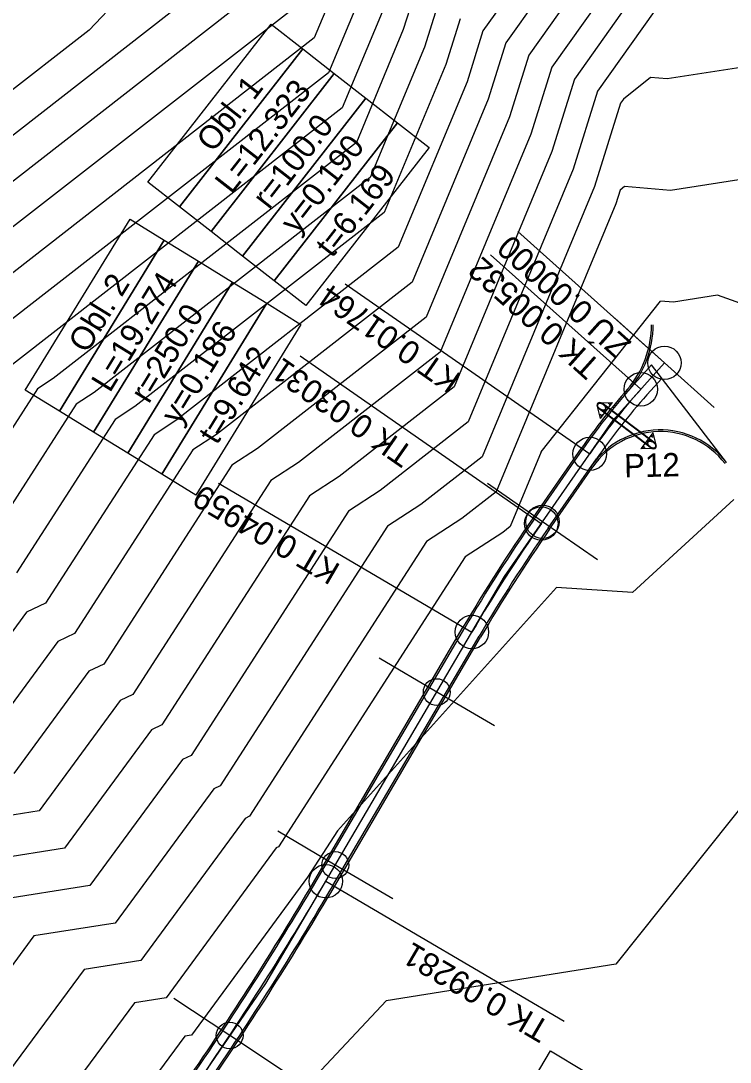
# Model space of a CAD drawing. Extents: x -549394 to -546608, y -1037055 to -1033629.
# Drawn here: x -548837.4 to -548731.3, y -1034470 to -1034314.2 of the extents above; entities that cross this region are included whole.
import ezdxf

# ---------------------------------------------------------------- set-up
doc = ezdxf.new("R2010")
doc.units = 0
for name, color, linetype in [('hlavni_vrst', 7, 'Continuous'), ('norm_vrst', 7, 'Continuous'), ('POLYGONY_SITUACE_PO', 7, 'Continuous'), ('u_sirka_0_5m', 7, 'Continuous'), ('u_sirka_1_0m', 7, 'Continuous'), ('x_navrh_C123', 7, 'Continuous'), ('x_osa_C123', 7, 'Continuous'), ('x_popis_C123', 7, 'Continuous'), ('x_popis_oblouky_C123', 7, 'Continuous'), ('x_popis_pricne_rezy_C123', 7, 'Continuous'), ('x_propustek', 7, 'Continuous')]:
    doc.layers.add(name, color=color, linetype=linetype)

msp = doc.modelspace()

# ---------------------------------------------------------------- linework, layer by layer
at = {"layer": 'hlavni_vrst'}
for p, q in [((-548811.72, -1034299.21), (-548827.23, -1034315.61)), ((-548762.75, -1034307.93), (-548768.28, -1034315.73)), ((-548786.57, -1034310.32), (-548791.42, -1034322)), ((-548742.68, -1034312.83), (-548751.12, -1034324.74)), ((-548827.23, -1034315.61), (-548875.4, -1034353.08)), ((-548768.28, -1034315.73), (-548770.67, -1034323.35)), ((-548791.42, -1034322), (-548844.83, -1034363.54)), ((-548770.67, -1034323.35), (-548780.95, -1034348.1)), ((-548751.12, -1034324.74), (-548754.77, -1034336.39)), ((-548754.77, -1034336.39), (-548770.49, -1034374.21)), ((-548780.95, -1034348.1), (-548814.25, -1034374.01)), ((-548814.25, -1034374.01), (-548817.51, -1034376.13)), ((-548770.49, -1034374.21), (-548783.68, -1034384.47)), ((-548817.51, -1034376.13), (-548833.75, -1034401.33)), ((-548783.68, -1034384.47), (-548788.4, -1034387.55)), ((-548788.4, -1034387.55), (-548811.96, -1034424.09)), ((-548833.75, -1034401.33), (-548836.59, -1034402.68)), ((-548836.59, -1034402.68), (-548846.11, -1034415.62)), ((-548722.62, -1034422.98), (-548748.38, -1034455.32)), ((-548813.23, -1034424.7), (-548827.11, -1034443.57)), ((-548811.96, -1034424.09), (-548813.23, -1034424.7)), ((-548827.11, -1034443.57), (-548843, -1034446.09)), ((-548748.38, -1034455.32), (-548782.79, -1034460.78)), ((-548782.79, -1034460.78), (-548798.95, -1034478.01))]:
    msp.add_line(p, q, dxfattribs=at)
at = {"layer": 'norm_vrst'}
for p, q in [((-548799.8, -1034301.11), (-548869.29, -1034355.17)), ((-548797.7, -1034306.33), (-548863.17, -1034357.27)), ((-548789.75, -1034307.71), (-548793.52, -1034316.78)), ((-548778.58, -1034310.32), (-548780.21, -1034315.53)), ((-548758.74, -1034308.91), (-548764.85, -1034317.53)), ((-548754.72, -1034309.89), (-548761.42, -1034319.34)), ((-548795.61, -1034311.56), (-548857.06, -1034359.36)), ((-548750.71, -1034310.87), (-548757.99, -1034321.14)), ((-548746.69, -1034311.85), (-548754.56, -1034322.94)), ((-548783.39, -1034312.92), (-548789.33, -1034327.22)), ((-548775.15, -1034312.13), (-548777.03, -1034318.14)), ((-548771.71, -1034313.93), (-548773.85, -1034320.75)), ((-548687.4, -1034314.52), (-548740.71, -1034322.92)), ((-548780.21, -1034315.53), (-548787.23, -1034332.44)), ((-548793.52, -1034316.78), (-548850.94, -1034361.45)), ((-548777.03, -1034318.14), (-548785.14, -1034337.66)), ((-548764.85, -1034317.53), (-548767.49, -1034325.96)), ((-548761.42, -1034319.34), (-548764.31, -1034328.57)), ((-548773.85, -1034320.75), (-548783.05, -1034342.88)), ((-548757.99, -1034321.14), (-548761.13, -1034331.17)), ((-548743.22, -1034322.7), (-548747.27, -1034325.94)), ((-548740.71, -1034322.92), (-548743.22, -1034322.7)), ((-548754.56, -1034322.94), (-548757.95, -1034333.78)), ((-548747.27, -1034325.94), (-548747.69, -1034326.55)), ((-548789.33, -1034327.22), (-548838.71, -1034365.64)), ((-548767.49, -1034325.96), (-548778.86, -1034353.32)), ((-548747.69, -1034326.55), (-548751.59, -1034339)), ((-548764.31, -1034328.57), (-548776.77, -1034358.54)), ((-548761.13, -1034331.17), (-548774.67, -1034363.76)), ((-548787.23, -1034332.44), (-548832.6, -1034367.73)), ((-548757.95, -1034333.78), (-548772.58, -1034368.98)), ((-548710.3, -1034334.9), (-548740.22, -1034339.62)), ((-548785.14, -1034337.66), (-548826.48, -1034369.82)), ((-548751.59, -1034339), (-548768.39, -1034379.43)), ((-548747.77, -1034339.56), (-548748.41, -1034341.6)), ((-548747.08, -1034339), (-548747.77, -1034339.56)), ((-548740.22, -1034339.62), (-548747.08, -1034339)), ((-548783.05, -1034342.88), (-548820.37, -1034371.91)), ((-548748.41, -1034341.6), (-548766.3, -1034384.65)), ((-548778.86, -1034353.32), (-548808.14, -1034376.1)), ((-548733.19, -1034355.28), (-548739.74, -1034356.32)), ((-548721.16, -1034359.52), (-548733.19, -1034355.28)), ((-548759.56, -1034378.68), (-548741.71, -1034356.14)), ((-548739.74, -1034356.32), (-548741.71, -1034356.14)), ((-548776.77, -1034358.54), (-548802.02, -1034378.19)), ((-548774.67, -1034363.76), (-548795.91, -1034380.28)), ((-548832.6, -1034367.73), (-548834.97, -1034369.28)), ((-548834.97, -1034369.28), (-548846.83, -1034387.66)), ((-548772.58, -1034368.98), (-548789.79, -1034382.37)), ((-548826.48, -1034369.82), (-548829.15, -1034371.56)), ((-548829.15, -1034371.56), (-548842.47, -1034392.22)), ((-548820.37, -1034371.91), (-548823.33, -1034373.85)), ((-548823.33, -1034373.85), (-548838.11, -1034396.77)), ((-548808.14, -1034376.1), (-548811.68, -1034378.41)), ((-548811.68, -1034378.41), (-548829.39, -1034405.88)), ((-548802.02, -1034378.19), (-548805.86, -1034380.7)), ((-548759.56, -1034378.68), (-548764.21, -1034389.87)), ((-548795.91, -1034380.28), (-548800.04, -1034382.98)), ((-548768.39, -1034379.43), (-548777.56, -1034386.56)), ((-548805.86, -1034380.7), (-548825.03, -1034410.43)), ((-548800.04, -1034382.98), (-548820.68, -1034414.99)), ((-548789.79, -1034382.37), (-548794.22, -1034385.26)), ((-548766.3, -1034384.65), (-548771.45, -1034388.65)), ((-548794.22, -1034385.26), (-548816.32, -1034419.54)), ((-548777.56, -1034386.56), (-548782.57, -1034389.83)), ((-548730.72, -1034385.83), (-548745.9, -1034399.75)), ((-548771.45, -1034388.65), (-548776.75, -1034392.12)), ((-548782.57, -1034389.83), (-548807.6, -1034428.65)), ((-548765.33, -1034390.74), (-548770.93, -1034394.4)), ((-548764.21, -1034389.87), (-548765.33, -1034390.74)), ((-548776.75, -1034392.12), (-548803.24, -1034433.2)), ((-548770.93, -1034394.4), (-548798.88, -1034437.75)), ((-548757.29, -1034399), (-548790.05, -1034435.37)), ((-548745.9, -1034399.75), (-548757.29, -1034399)), ((-548829.39, -1034405.88), (-548831.92, -1034407.08)), ((-548831.92, -1034407.08), (-548842.31, -1034421.21)), ((-548827.25, -1034411.48), (-548838.51, -1034426.8)), ((-548825.03, -1034410.43), (-548827.25, -1034411.48)), ((-548822.58, -1034415.89), (-548834.71, -1034432.39)), ((-548820.68, -1034414.99), (-548822.58, -1034415.89)), ((-548817.9, -1034420.29), (-548830.91, -1034437.98)), ((-548816.32, -1034419.54), (-548817.9, -1034420.29)), ((-548807.6, -1034428.65), (-548808.56, -1034429.1)), ((-548808.56, -1034429.1), (-548823.31, -1034449.17)), ((-548834.71, -1034432.39), (-548858.04, -1034436.09)), ((-548803.24, -1034433.2), (-548803.88, -1034433.51)), ((-548803.88, -1034433.51), (-548819.51, -1034454.76)), ((-548790.05, -1034435.37), (-548794.52, -1034442.31)), ((-548830.91, -1034437.98), (-548850.52, -1034441.09)), ((-548799.21, -1034437.91), (-548815.71, -1034460.35)), ((-548798.88, -1034437.75), (-548799.21, -1034437.91)), ((-548794.54, -1034442.31), (-548811.91, -1034465.94)), ((-548794.52, -1034442.31), (-548794.54, -1034442.31)), ((-548823.31, -1034449.17), (-548835.48, -1034451.1)), ((-548835.48, -1034451.1), (-548849.27, -1034469.67)), ((-548819.51, -1034454.76), (-548827.96, -1034456.1)), ((-548827.96, -1034456.1), (-548842.93, -1034476.26)), ((-548820.43, -1034461.1), (-548836.58, -1034482.84)), ((-548815.71, -1034460.35), (-548820.43, -1034461.1)), ((-548812.91, -1034466.1), (-548830.24, -1034489.43)), ((-548811.91, -1034465.94), (-548812.91, -1034466.1))]:
    msp.add_line(p, q, dxfattribs=at)
at = {"layer": 'POLYGONY_SITUACE_PO'}
for centre in [(-548741.12, -1034365.38), (-548744.67, -1034369.34), (-548752.31, -1034379), (-548759.55, -1034389.41), (-548769.93, -1034405.64), (-548791.8, -1034442.92)]:
    msp.add_circle(centre, 2.5, dxfattribs=at)
at = {"layer": 'u_sirka_0_5m'}
for centre in [(-548775.2, -1034414.62), (-548790.38, -1034440.49), (-548806.19, -1034465.98)]:
    msp.add_circle(centre, 2, dxfattribs=at)
at = {"layer": 'u_sirka_1_0m'}
msp.add_circle((-548759.37, -1034389.15), 2.5, dxfattribs=at)
at = {"layer": 'x_navrh_C123'}
for p, q in [((-548745.6, -1034368.51), (-548743.07, -1034365.69)), ((-548743.74, -1034370.17), (-548741.52, -1034367.7)), ((-548760.57, -1034388.69), (-548753.34, -1034378.29)), ((-548758.52, -1034390.12), (-548751.28, -1034379.72)), ((-548758.31, -1034390.26), (-548751.82, -1034380.92)), ((-548792.88, -1034442.29), (-548771.01, -1034405)), ((-548790.73, -1034443.55), (-548768.85, -1034406.27))]:
    msp.add_line(p, q, dxfattribs=at)
for points in [[(-548760.78, -1034388.55), (-548753.54, -1034378.15)], [(-548793.1, -1034442.16), (-548771.22, -1034404.88)], [(-548790.51, -1034443.68), (-548768.64, -1034406.4)]]:
    msp.add_lwpolyline(points, dxfattribs=at)
for centre, radius, start, end in [((-548757.81, -1034359.68), 14.75, 318.8997, 0), ((-548757.81, -1034359.68), 15, 318.8997, 0), ((-548670.21, -1034436.1), 101.5, 138.8997, 145.1827), ((-548670.21, -1034436.1), 101.25, 138.1192, 145.1827), ((-548670.21, -1034436.1), 98.75, 138.1192, 145.1827), ((-548741.76, -1034387.91), 12.5, 37.5364, 145.1827), ((-548741.76, -1034387.91), 12.25, 37.5364, 145.1827), ((-548554.3, -1034532.15), 251.5, 145.1827, 149.6), ((-548554.3, -1034532.15), 251.5, 145.1827, 149.6), ((-548554.3, -1034532.15), 251.25, 145.1827, 149.6), ((-548554.3, -1034532.15), 248.75, 145.1827, 149.6), ((-548554.3, -1034532.15), 248.5, 145.1827, 149.6), ((-549223.06, -1034189.9), 498.5, 325.5454, 329.6), ((-549223.06, -1034189.9), 498.75, 325.5454, 329.6), ((-549223.06, -1034189.9), 501.25, 325.5454, 329.6), ((-549223.06, -1034189.9), 501.5, 325.5454, 329.6)]:
    msp.add_arc(centre, radius, start, end, dxfattribs=at)
at = {"layer": 'x_osa_C123'}
msp.add_lwpolyline([(-548848.64, -1034527.97), (-548800.76, -1034458.19), (-548765.05, -1034397.32), (-548748.79, -1034373.93), (-548741.12, -1034365.38)], dxfattribs=at)
for centre, radius, start, end in [((-548670.21, -1034436.1), 100, 138.1192, 145.1827), ((-548554.3, -1034532.15), 250, 145.1827, 149.6), ((-549223.06, -1034189.9), 500, 325.5454, 329.6)]:
    msp.add_arc(centre, radius, start, end, dxfattribs=at)
at = {"layer": 'x_popis_oblouky_C123'}
msp.add_line((-548731.85, -1034380.3), (-548743.07, -1034365.69), dxfattribs=at)
for points in [[(-548818.44, -1034338.37), (-548799.99, -1034314.72), (-548795.26, -1034318.41), (-548813.71, -1034342.06)], [(-548813.71, -1034342.06), (-548795.26, -1034318.41), (-548790.53, -1034322.1), (-548808.98, -1034345.75)], [(-548808.98, -1034345.75), (-548790.53, -1034322.1), (-548785.8, -1034325.79), (-548804.25, -1034349.44)], [(-548804.25, -1034349.44), (-548785.8, -1034325.79), (-548781.07, -1034329.48), (-548799.52, -1034353.13)], [(-548799.52, -1034353.13), (-548781.07, -1034329.48), (-548776.34, -1034333.17), (-548794.79, -1034356.82)], [(-548836.79, -1034369.47), (-548821.08, -1034343.91), (-548815.97, -1034347.05), (-548831.68, -1034372.61)], [(-548831.68, -1034372.61), (-548815.97, -1034347.05), (-548810.86, -1034350.19), (-548826.56, -1034375.75)], [(-548826.56, -1034375.75), (-548810.86, -1034350.19), (-548805.75, -1034353.33), (-548821.45, -1034378.89)], [(-548821.45, -1034378.89), (-548805.75, -1034353.33), (-548800.63, -1034356.47), (-548816.34, -1034382.03)], [(-548816.34, -1034382.03), (-548800.63, -1034356.47), (-548795.52, -1034359.62), (-548811.23, -1034385.18)], [(-548753.01, -1034471.35), (-548768.32, -1034497.14), (-548773.48, -1034494.08), (-548758.17, -1034468.28)]]:
    msp.add_lwpolyline(points, close=True, dxfattribs=at)
for points in [[(-548763.05, -1034345.72), (-548741.12, -1034365.38)], [(-548767.13, -1034349.2), (-548744.67, -1034369.34)], [(-548788.9, -1034353.55), (-548752.31, -1034379)], [(-548795.63, -1034364.31), (-548759.55, -1034389.41)], [(-548807.84, -1034383.39), (-548769.93, -1034405.64)], [(-548791.8, -1034442.92), (-548756.12, -1034463.86)]]:
    msp.add_lwpolyline(points, dxfattribs=at)
at = {"layer": 'x_popis_pricne_rezy_C123'}
for points in [[(-548733.67, -1034372.06), (-548741.12, -1034365.38), (-548748.56, -1034358.71)], [(-548751.16, -1034394.86), (-548759.37, -1034389.15), (-548767.58, -1034383.44)], [(-548766.57, -1034419.68), (-548775.2, -1034414.62), (-548783.82, -1034409.56)], [(-548781.75, -1034445.55), (-548790.38, -1034440.49), (-548799, -1034435.43)], [(-548797.85, -1034471.51), (-548806.19, -1034465.98), (-548814.53, -1034460.46)]]:
    msp.add_lwpolyline(points, dxfattribs=at)
at = {"layer": 'x_propustek'}
for p, q in [((-548750.95, -1034371.35), (-548751.2, -1034371.69)), ((-548750.68, -1034373.7), (-548751.2, -1034371.69)), ((-548750.95, -1034371.35), (-548748.87, -1034371.31)), ((-548743.31, -1034378.01), (-548750.83, -1034372.32)), ((-548743.26, -1034377.95), (-548750.78, -1034372.26)), ((-548750.68, -1034373.7), (-548748.87, -1034371.31)), ((-548742.76, -1034377.29), (-548750.29, -1034371.6)), ((-548742.72, -1034377.23), (-548750.24, -1034371.54)), ((-548749.16, -1034371.68), (-548749.48, -1034371.44)), ((-548749.22, -1034371.76), (-548749.38, -1034371.64)), ((-548749.1, -1034371.6), (-548749.26, -1034371.48)), ((-548750.4, -1034373.32), (-548750.72, -1034373.08)), ((-548750.46, -1034373.4), (-548750.62, -1034373.28)), ((-548750.34, -1034373.24), (-548750.5, -1034373.12)), ((-548742.87, -1034375.85), (-548744.67, -1034378.24)), ((-548743.21, -1034376.31), (-548743.05, -1034376.43)), ((-548743.15, -1034376.23), (-548742.83, -1034376.47)), ((-548743.09, -1034376.15), (-548742.93, -1034376.27)), ((-548742.87, -1034375.85), (-548742.35, -1034377.86)), ((-548742.6, -1034378.19), (-548744.67, -1034378.24)), ((-548744.45, -1034377.95), (-548744.29, -1034378.07)), ((-548744.39, -1034377.87), (-548744.07, -1034378.11)), ((-548744.33, -1034377.79), (-548744.17, -1034377.91)), ((-548742.6, -1034378.19), (-548742.35, -1034377.86))]:
    msp.add_line(p, q, dxfattribs=at)
for points in [[(-548751.13, -1034371.48), (-548751.14, -1034371.49), (-548751.15, -1034371.5), (-548751.17, -1034371.53), (-548751.17, -1034371.55), (-548751.19, -1034371.59), (-548751.2, -1034371.62), (-548751.21, -1034371.73), (-548751.2, -1034371.8), (-548751.14, -1034371.96), (-548751.1, -1034372.04), (-548750.98, -1034372.19), (-548750.91, -1034372.26), (-548750.75, -1034372.38), (-548750.66, -1034372.43), (-548750.49, -1034372.5), (-548750.4, -1034372.52), (-548750.23, -1034372.53), (-548750.15, -1034372.52), (-548750.07, -1034372.49), (-548750.06, -1034372.48), (-548750.03, -1034372.47), (-548750.02, -1034372.46), (-548749.98, -1034372.43), (-548749.95, -1034372.41), (-548749.93, -1034372.38)], [(-548749.93, -1034372.38), (-548749.93, -1034372.37), (-548749.92, -1034372.36), (-548749.9, -1034372.33), (-548749.9, -1034372.32), (-548749.88, -1034372.27), (-548749.87, -1034372.24), (-548749.86, -1034372.14), (-548749.87, -1034372.06), (-548749.93, -1034371.9), (-548749.97, -1034371.82), (-548750.09, -1034371.67), (-548750.16, -1034371.6), (-548750.32, -1034371.48), (-548750.41, -1034371.43), (-548750.58, -1034371.36), (-548750.67, -1034371.34), (-548750.84, -1034371.33), (-548750.92, -1034371.34), (-548751, -1034371.37), (-548751.01, -1034371.38), (-548751.04, -1034371.39), (-548751.05, -1034371.4), (-548751.09, -1034371.43), (-548751.12, -1034371.45), (-548751.13, -1034371.48)], [(-548751.07, -1034371.52), (-548751.09, -1034371.54), (-548751.1, -1034371.56), (-548751.12, -1034371.61), (-548751.12, -1034371.64), (-548751.13, -1034371.69), (-548751.13, -1034371.72), (-548751.12, -1034371.79), (-548751.11, -1034371.82), (-548751.09, -1034371.89), (-548751.07, -1034371.93), (-548751.03, -1034372), (-548751.01, -1034372.03), (-548750.93, -1034372.14), (-548750.86, -1034372.2), (-548750.71, -1034372.32), (-548750.63, -1034372.36), (-548750.51, -1034372.41), (-548750.47, -1034372.42), (-548750.39, -1034372.44), (-548750.35, -1034372.45), (-548750.27, -1034372.45), (-548750.24, -1034372.45), (-548750.17, -1034372.44), (-548750.14, -1034372.44), (-548750.09, -1034372.42), (-548750.07, -1034372.4), (-548750.03, -1034372.37), (-548750.01, -1034372.36), (-548749.98, -1034372.32), (-548749.97, -1034372.3), (-548749.95, -1034372.25), (-548749.95, -1034372.23), (-548749.94, -1034372.17), (-548749.94, -1034372.14), (-548749.95, -1034372.08), (-548749.96, -1034372.04), (-548749.98, -1034371.97), (-548750, -1034371.93), (-548750.04, -1034371.86), (-548750.06, -1034371.83), (-548750.14, -1034371.72), (-548750.21, -1034371.66), (-548750.36, -1034371.54), (-548750.44, -1034371.5), (-548750.56, -1034371.45), (-548750.6, -1034371.44), (-548750.68, -1034371.42), (-548750.72, -1034371.41), (-548750.8, -1034371.41), (-548750.83, -1034371.41), (-548750.9, -1034371.42), (-548750.93, -1034371.42), (-548750.98, -1034371.44), (-548751, -1034371.46), (-548751.04, -1034371.49), (-548751.06, -1034371.5), (-548751.07, -1034371.52)], [(-548743.61, -1034377.16), (-548743.62, -1034377.18), (-548743.63, -1034377.19), (-548743.65, -1034377.22), (-548743.65, -1034377.23), (-548743.67, -1034377.28), (-548743.68, -1034377.31), (-548743.69, -1034377.41), (-548743.68, -1034377.49), (-548743.62, -1034377.65), (-548743.57, -1034377.73), (-548743.46, -1034377.88), (-548743.39, -1034377.95), (-548743.23, -1034378.07), (-548743.14, -1034378.12), (-548742.97, -1034378.19), (-548742.88, -1034378.21), (-548742.71, -1034378.22), (-548742.63, -1034378.21), (-548742.55, -1034378.18), (-548742.54, -1034378.17), (-548742.51, -1034378.16), (-548742.49, -1034378.15), (-548742.46, -1034378.12), (-548742.43, -1034378.1), (-548742.41, -1034378.07)], [(-548742.41, -1034378.07), (-548742.4, -1034378.06), (-548742.4, -1034378.05), (-548742.38, -1034378.02), (-548742.37, -1034378), (-548742.36, -1034377.96), (-548742.35, -1034377.93), (-548742.34, -1034377.82), (-548742.35, -1034377.75), (-548742.41, -1034377.59), (-548742.45, -1034377.51), (-548742.57, -1034377.36), (-548742.64, -1034377.29), (-548742.8, -1034377.17), (-548742.89, -1034377.12), (-548743.06, -1034377.05), (-548743.15, -1034377.03), (-548743.32, -1034377.02), (-548743.39, -1034377.03), (-548743.47, -1034377.06), (-548743.49, -1034377.06), (-548743.52, -1034377.08), (-548743.53, -1034377.09), (-548743.57, -1034377.12), (-548743.59, -1034377.14), (-548743.61, -1034377.16)], [(-548742.47, -1034378.03), (-548742.46, -1034378.01), (-548742.45, -1034377.99), (-548742.43, -1034377.94), (-548742.42, -1034377.91), (-548742.42, -1034377.86), (-548742.42, -1034377.83), (-548742.43, -1034377.76), (-548742.44, -1034377.73), (-548742.46, -1034377.66), (-548742.48, -1034377.62), (-548742.52, -1034377.55), (-548742.54, -1034377.51), (-548742.62, -1034377.41), (-548742.69, -1034377.34), (-548742.84, -1034377.23), (-548742.92, -1034377.19), (-548743.04, -1034377.14), (-548743.08, -1034377.12), (-548743.16, -1034377.1), (-548743.2, -1034377.1), (-548743.28, -1034377.09), (-548743.31, -1034377.1), (-548743.38, -1034377.1), (-548743.41, -1034377.11), (-548743.46, -1034377.13), (-548743.48, -1034377.14), (-548743.52, -1034377.17), (-548743.54, -1034377.19), (-548743.57, -1034377.23), (-548743.58, -1034377.25), (-548743.6, -1034377.3), (-548743.6, -1034377.32), (-548743.61, -1034377.38), (-548743.61, -1034377.41), (-548743.6, -1034377.47), (-548743.59, -1034377.51), (-548743.56, -1034377.58), (-548743.55, -1034377.61), (-548743.51, -1034377.69), (-548743.48, -1034377.72), (-548743.4, -1034377.83), (-548743.34, -1034377.89), (-548743.19, -1034378), (-548743.11, -1034378.05), (-548742.98, -1034378.1), (-548742.94, -1034378.11), (-548742.86, -1034378.13), (-548742.83, -1034378.14), (-548742.75, -1034378.14), (-548742.72, -1034378.14), (-548742.65, -1034378.13), (-548742.62, -1034378.12), (-548742.57, -1034378.1), (-548742.55, -1034378.09), (-548742.51, -1034378.06), (-548742.49, -1034378.05), (-548742.47, -1034378.03)]]:
    msp.add_open_spline(points, degree=3, dxfattribs=at)

# ---------------------------------------------------------------- texts
at = {"layer": 'x_popis_C123'}
msp.add_text('P12', height=3.5, rotation=1.225, dxfattribs=at).set_placement((-548747.12, -1034382.52))
at = {"layer": 'x_popis_oblouky_C123'}
for s, rotation, p in [('Obl. 1', 52.0615, (-548808.67, -1034334.06)), ('L=12.323', 52.0615, (-548805.91, -1034340.28)), ('r=100.0', 52.0615, (-548800.31, -1034342.57)), ('y=0.190', 52.0615, (-548796.15, -1034346.27)), ('t=6.169', 52.0615, (-548790.85, -1034349.81)), ('ZÚ 0.00000', 138.1192, (-548745.91, -1034362.34)), ('TK 0.00532', 138.1192, (-548750.44, -1034365.46)), ('Obl. 2', 58.451, (-548827.55, -1034364.1)), ('L=19.274', 58.451, (-548824.12, -1034369.97)), ('KT 0.01764', 145.1827, (-548771.33, -1034367.25)), ('r=250.0', 58.451, (-548818.3, -1034371.63)), ('y=0.186', 58.451, (-548813.75, -1034374.84)), ('t=9.642', 58.451, (-548808.09, -1034377.77)), ('TK 0.03031', 145.1827, (-548778.41, -1034378.3)), ('KT 0.04959', 149.6, (-548789.42, -1034395.69)), ('TK 0.09281', 149.6, (-548757.99, -1034464.16))]:
    msp.add_text(s, height=3.5, rotation=rotation, dxfattribs=at).set_placement(p)

doc.saveas('drawing.dxf')
